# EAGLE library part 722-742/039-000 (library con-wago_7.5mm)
Serie 722, Federleiste mit Verriegelungsklinken / Series 722, Female connector with locking levers Polzahl / Pole No.: 12 Bemessungsspannung / Rated Voltage: 400 V Nennstrom / Nominal Current: 12 A Farbe / Color: xxxx / xxxx Stand: 01.01.2012. Die jeweils aktuellen Daten zu diesem Artikel finden Sie in unserem Produktkatalog, den Sie unter www.wago.com einsehen können. As of: 01/01/2012. Please find the newest data for this article in our product catalogue, which can be viewed under www.wago.com.
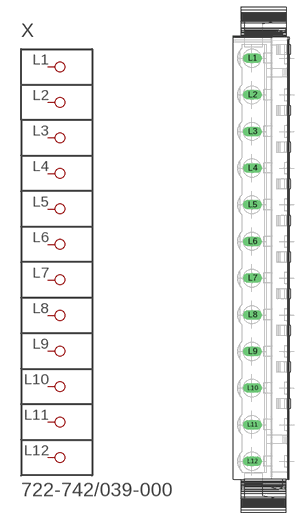
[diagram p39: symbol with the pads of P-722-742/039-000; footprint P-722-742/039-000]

Designator prefix X

## 722-742/039-000  [P-722-742/039-000]
L1  P1
L2  P2
L3  P3
L4  P4
L5  P5
L6  P6
L7  P7
L8  P8
L9  P9
L10  P10
L11  P11
L12  P12

## Footprint P-722-742/039-000 (pad centres in mm)
drill 1.3 long: L1 -2.271,41.25; L2 -2.271,33.75; L3 -2.271,26.25; L4 -2.271,18.75; L5 -2.271,11.25; L6 -2.271,3.75; L7 -2.271,-3.75; L8 -2.271,-11.25; L9 -2.271,-18.75; L10 -2.271,-26.25; L11 -2.271,-33.75; L12 -2.271,-41.25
